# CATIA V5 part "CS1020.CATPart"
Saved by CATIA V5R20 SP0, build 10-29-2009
Part number: CS1020
Revision: 6
Definition: design
Nomenclature: CS1020
Source: made
Description: NOT SPECIFIED
Bounding box of the stored display mesh (mm): x -18.807 to 19, y -19 to 19, z -36 to 9
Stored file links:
  C:\Users\Raffaele\Desktop\3D X SITO CF\BOLEX\20-TILTED COLUMN SUPPORT\CS1020.CATPart
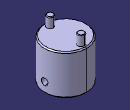
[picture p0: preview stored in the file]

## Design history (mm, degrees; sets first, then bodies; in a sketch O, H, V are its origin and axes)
Body1 "MANIFOLD_SOLID_BREP #695" (main body)
  Solid1: solid without history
